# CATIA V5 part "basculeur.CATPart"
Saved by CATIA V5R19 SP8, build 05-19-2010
Part number: basculeur
Bounding box of the stored display mesh (mm): x 0 to 180, y -100 to 55, z 0 to 204.93
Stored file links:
  F:\CFAO\Hberriche\basculeur.CATPart
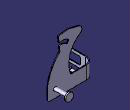
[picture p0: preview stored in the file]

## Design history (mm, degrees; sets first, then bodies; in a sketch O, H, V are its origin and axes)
Body1 (main body)
  Sketch1 on xy-plane, origin (0, 0, 0), H (1, 0, 0), V (0, 1, 0)
    line L1 (0, -100) -> (0, -30)
    line L2 (30, 0) -> (180, 0)
    arc A1 centre (30, -30) radius 30 from (0, -30) to (30, 0) cw
    radius A1 = 30
    length L2 = 150
    length L1 = 70
    vertical: L1 V
    horizontal: L2 H
    tangency: A1 L1, A1 L2
    coincidence: V L1, H L2
  Pad1: profile Sketch1, direction (0, 0, 1), length 50, thin wall 3
  Sketch2 on face of Pad1, origin (0, 0, 0), H (-1, 0, 0), V (0, 0, 1)
    point P1 (-5828.9483, 1652.924)
    arc A1 centre (-12.6418, 26.3044) radius 169.0273 from (-180, 50) to (-132.9069, 145.0754) cw
    point P3 (-180, 50)
    point P4 (-132.9069, 145.0754)
    line L1 (-180, 50) -> (-90.7196, 50)
    arc A2 centre (5.4523, 86.6795) radius 102.9293 from (-90.7196, 50) to (-86.7595, 132.4116) cw
    line L2 (-138.0895, 200.707) -> (-96.6571, 204.9862)
    line L3 (-96.6571, 204.9862) -> (-58.0925, 194.914)
    point P10 (-58.0925, 194.914)
    arc A3 centre (-62.4438, 180.559) radius 15 from (-58.0925, 194.914) to (-55.8005, 167.1103) cw
    point P12 (-58.0925, 194.914)
    arc A4 centre (-8.126, 93.4136) radius 87.7728 from (-86.7595, 132.4116) to (-55.8005, 167.1103) cw
    line L4 (-138.0895, 200.707) -> (-132.9069, 145.0754)
    point P15 (-132.9069, 145.0754)
    reference projected line E1 (-30, 50) -> (-180, 50) from edge [end face of Pad1 | face of Pad1]
    reference projected line E2 (-180, 0) -> (-180, 50) from edge [face of Pad1 | face of Pad1]
    radius A3 = 15
    horizontal: L1 H
    tangency: A4 A2
    coincidence: P4 P15, E1 L1, E2 P3, P10 P12
  Pad2: profile Sketch2, direction (0, -1, 0), length 3
  Fillet1: radius 10, on edge [start face of Pad1 | face of Pad1]
  Fillet2: radius 5, on edge [end face of Pad1 | face of Pad2 from Sketch2.A2]
  Fillet3: radius 5, on edge [face of Pad2 from Sketch2.L4 | face of Pad2 from Sketch2.A1]
  Fillet4: radius 3, on edge [face of Pad2 from Sketch2.L2 | face of Pad2 from Sketch2.L4]
  Fillet5: radius 3, on edge [face of Pad2 from Sketch2.L3 | face of Pad2 from Sketch2.L2]
  Sketch3 on face of Pad2, origin (0, 0, 0), H (-1, 0, 0), V (0, 0, 1)
    circle A1 centre (-149.8524, 29.9746) radius 7.5
    reference projected curve E1 from edge of DatumCurve1
    radius A1 = 7.5
    concentricity: E1 A1
  Pad3: profile Sketch3, direction (0, 1, 0), length 50
  Sketch4 on end face of Pad3, origin (0, 50, 0), H (-1, 0, 0), V (0, 0, 1)
    circle A1 centre (-149.8524, 29.9746) radius 15
    reference projected circle E1 centre (-149.8524, 29.9746) radius 7.5 from edge [face of Pad3 from Sketch3.A1 | end face of Pad3]
    radius A1 = 15
    concentricity: E1 A1
  Pad4: profile Sketch4, direction (0, 1, 0), length 5
  Sketch5 on face of Pad2, origin (0, 0, 0), H (-1, 0, 0), V (0, 0, 1)
    line L1 (-134.7679, 165.0527) -> (-135.8476, 176.642)
    point P1 (-134.7679, 165.0527)
    point P2 (-135.8476, 176.642)
    spline S1 through (-135.8476, 176.642) (-122.6994, 178.6033) (-108.537, 176.0157) (-98.0009, 168.9752)
    spline S2 through (-134.7679, 165.0527) (-120.5098, 166.6051) (-108.7073, 161.4976) (-103.8853, 158.1816)
    line L2 (-98.0009, 168.9752) -> (-103.8853, 158.1816)
    point P3 (-98.0009, 168.9752)
    point P4 (-103.8853, 158.1816)
    reference projected line E1 (-138.0895, 200.707) -> (-132.9069, 145.0754) from edge [face of Pad2 from Sketch2.L4 | face of Pad2]
    point P5 (-134.7679, 165.0527)
    point P6 (-98.0009, 168.9752)
    point P7 (-135.8476, 176.642)
    point P8 (-103.8853, 158.1816)
    coincidence: P1 P5, P6 P3, P4 S2, E1 L1, P2 P7, P8 P4
  Pocket1: profile Sketch5, direction (0, -1, 0), through (limit type 3)
  Sketch6 on face of Pad2, origin (0, -3, 0), H (1, 0, 0), V (0, 0, 1)
    circle A1 centre (65.3211, 39.2397) radius 5
    radius A1 = 5
  Pad5: profile Sketch6, direction (0, -1, 0), length 20
  Sketch7 on end face of Pad5, origin (0, -23, 0), H (1, 0, 0), V (0, 0, 1)
    circle A1 centre (65.3211, 39.2397) radius 7.5
    reference projected circle E1 centre (65.3211, 39.2397) radius 5 from edge [face of Pad5 from Sketch6.A1 | end face of Pad5]
    radius A1 = 7.5
    concentricity: E1 A1
  Pad6: profile Sketch7, direction (0, -1, 0), length 5
  Sketch8 on face of Pad1, origin (0, 0, 0), H (0, -1, 0), V (0, 0, 1)
    line L1 (50, 40) -> (100, 40)
    line L2 (100, 40) -> (100, 10)
    line L3 (100, 10) -> (50, 10)
    line L4 (50, 10) -> (50, 40)
    reference projected line E1 (100, 0) -> (100, 50) from edge [face of Pad1 | face of Pad1]
    reference projected line E2 (100, 50) -> (30, 50) from edge [end face of Pad1 | face of Pad1]
    length L1 = 50
    length L2 = 30
    distance E2 L1 = 10
    horizontal: L1 H, L3 H
    vertical: L2 V, L4 V
    coincidence: E1 L2
  Pocket2: profile Sketch8, direction (1, 0, 0), through (limit type 3)
  Fillet6: radius 3, on edge [face of Pocket2 from Sketch8.L3 | face of Pocket2 from Sketch8.L4]
  Fillet7: radius 3, on edge [face of Pocket2 from Sketch8.L4 | face of Pocket2 from Sketch8.L1]
  Fillet8: radius 3, on edge [start face of Pad1 | face of Pad1]; edge [face of Pad1 | face of Pocket2 from Sketch8.L3]; edge [face of Pocket2 from Sketch8.L1 | face of Pad1]; edge [face of Pad1 | end face of Pad1]
  DatumCurve1
  Sketch9 on face of Pad2, origin (0, 0, 0), H (1, 0, 0), V (0, 0, -1)
    line L1 (0, -100) -> (0, -30)
    line L2 (30, 0) -> (180, 0)
    arc A1 centre (30, -30) radius 30 from (0, -30) to (30, 0) cw
    radius A1 = 30
    length L2 = 150
    length L1 = 70
    vertical: L1 V
    horizontal: L2 H
    tangency: A1 L1, A1 L2
    coincidence: V L1, H L2
  Pad7: profile Sketch9, direction (0, 1, 0), length 50, thin wall 3
  Sketch10 on face of Pad2, origin (0, 0, 0), H (1, 0, 0), V (0, 0, -1)
    line L1 (0, -100) -> (0, -30)
    line L2 (30, 0) -> (180, 0)
    arc A1 centre (30, -30) radius 30 from (0, -30) to (30, 0) cw
    radius A1 = 30
    length L2 = 150
    length L1 = 70
    vertical: L1 V
    horizontal: L2 H
    tangency: A1 L1, A1 L2
    coincidence: V L1, H L2
  Pad8: profile Sketch10, direction (0, 1, 0), length 50, thin wall 3
Current feature: Fillet8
